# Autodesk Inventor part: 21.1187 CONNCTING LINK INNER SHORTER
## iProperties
Created: 2007-08
Part Number: 21.1187 CONNCTING LINK INNER SHORTER
Material: Steel
Document SubType Name: Modeling
Designer: Andy Moles
Mass: 4.27124 g
Surface Area: 10.9751 cm^2
Volume: 0.544107 cm^3
Density: 7.85 g/cm^3
Author: Andy Moles
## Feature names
1. Extrusion1
2. Extrusion2
3. Extrusion3
